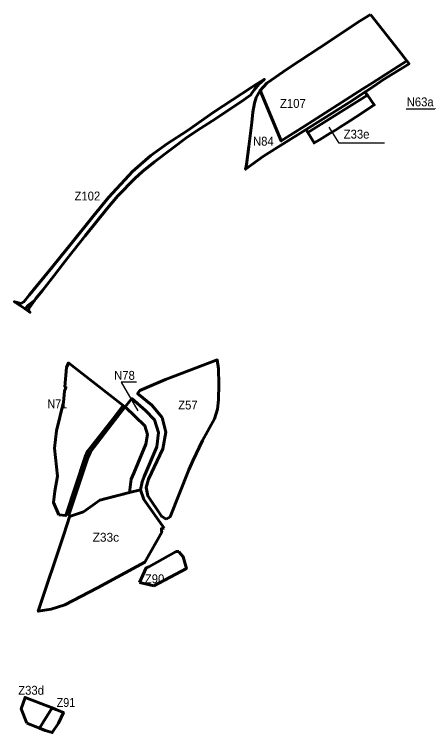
# Model space of a CAD drawing. Extents: x -650277 to -643425, y -1073980 to -1066720.
# Drawn here: x -648583 to -647467, y -1073980 to -1072042 of the extents above; entities that cross this region are included whole.
import ezdxf

# ---------------------------------------------------------------- set-up
doc = ezdxf.new("R2010")
doc.units = 0
doc.header["$LTSCALE"] = 9.6
for name, color, linetype, lineweight in [('15', 7, 'Continuous', 60), ('2', 7, 'Continuous', 40), ('24', 7, 'Continuous', 60), ('34', 7, 'Continuous', 60), ('42', 7, 'Continuous', 60), ('45', 7, 'Continuous', 60), ('48', 7, 'Continuous', 60), ('5', 7, 'Continuous', 60), ('59', 7, 'Continuous', 25), ('6', 7, 'Continuous', 60), ('60', 7, 'Continuous', 60), ('63', 7, 'Continuous', 25), ('8', 7, 'Continuous', 60), ('9', 7, 'Continuous', 60)]:
    doc.layers.add(name, color=color, linetype=linetype, lineweight=lineweight)

msp = doc.modelspace()

# ---------------------------------------------------------------- linework, layer by layer
at = {"layer": '15'}
msp.add_lwpolyline([(-647795.4, -1072352.415), (-647679.66, -1072279.15), (-647637.082, -1072251.377), (-647629.67, -1072259.82), (-647791.198, -1072360.119)], close=True, dxfattribs=at)
at = {"layer": '2', "lineweight": 60}
msp.add_lwpolyline([(-648303.791, -1072531.792), (-648258.165, -1072484.283), (-648237.406, -1072465.811), (-648205.298, -1072439.308), (-648116.32, -1072373.44), (-648079.76, -1072348.46), (-648050.276, -1072330.025), (-647969.894, -1072276.479), (-647944.45, -1072258.458), (-647941.77, -1072254.45), (-647934.9, -1072244.55), (-647923.16, -1072229.85), (-647908.5, -1072217.29), (-647933.95, -1072233.18), (-647942.21, -1072238.54), (-648046.69, -1072306.3), (-648117.12, -1072356), (-648169.81, -1072390.035), (-648214.73, -1072422.41), (-648264.618, -1072466.244), (-648274.53, -1072476.196), (-648328.847, -1072535.816), (-648369.37, -1072585.645), (-648431.557, -1072662.77), (-648459.243, -1072696.417), (-648481.468, -1072723.736), (-648543.255, -1072800.016), (-648557.588, -1072817.727), (-648565.726, -1072822.048), (-648583.407, -1072817.256), (-648564.86, -1072829.45), (-648554.22, -1072836.89), (-648541.102, -1072846.281), (-648545.462, -1072840.329), (-648544.632, -1072835.177), (-648524.979, -1072808.383), (-648507.503, -1072786.605), (-648476.204, -1072746.1), (-648452.274, -1072715.637), (-648439.912, -1072699.826), (-648391.796, -1072639.344), (-648333.178, -1072565.837)], close=True, dxfattribs=at)
at = {"layer": '24'}
msp.add_lwpolyline([(-648549.76, -1073954.86), (-648515.333, -1073968.584), (-648498, -1073940), (-648481.749, -1073913.76), (-648554.42, -1073885.092), (-648564.75, -1073915.91)], close=True, dxfattribs=at)
at = {"layer": '34'}
for points in [[(-647621.97, -1072041.73), (-647649.76, -1072059.06), (-647683.63, -1072081.94), (-647730.53, -1072112.84), (-647814.58, -1072167.67), (-647845.58, -1072188.94), (-647901.91, -1072227.6), (-647919.68, -1072247.09), (-647862.615, -1072383.084)], [(-647523.71, -1072167.071), (-647545.44, -1072139.35), (-647621.97, -1072041.73)], [(-647862.615, -1072383.084), (-647800.2, -1072343.615), (-647642.504, -1072242.974), (-647616.719, -1072226.154), (-647523.71, -1072167.071)]]:
    msp.add_lwpolyline(points, dxfattribs=at)
at = {"layer": '42'}
for points in [[(-647637.082, -1072251.377), (-647611.306, -1072234.563), (-647589.02, -1072219.66), (-647517.51, -1072174.98), (-647523.71, -1072167.071), (-647616.719, -1072226.154), (-647642.504, -1072242.974), (-647800.2, -1072343.615)], [(-647800.2, -1072343.615), (-647862.615, -1072383.084), (-647919.68, -1072247.09), (-647930.36, -1072266.38), (-647934.86, -1072280.99), (-647939.26, -1072306.1), (-647942.54, -1072333.82), (-647950.2, -1072398.61), (-647956.786, -1072446.511), (-647958.82, -1072459.74), (-647910.27, -1072424.51), (-647857.52, -1072391.14), (-647795.4, -1072352.415)], [(-647795.4, -1072352.415), (-647679.66, -1072279.15), (-647637.082, -1072251.377)]]:
    msp.add_lwpolyline(points, dxfattribs=at)
at = {"layer": '45'}
for points in [[(-648463.25, -1073392.125), (-648444.523, -1073394.235), (-648392.43, -1073235.98), (-648384.6, -1073219.54), (-648315.955, -1073131.889), (-648289.148, -1073097.66), (-648437.643, -1072982.601), (-648442.187, -1072994.5), (-648447.043, -1073046.967), (-648444.11, -1073048.69), (-648448.1, -1073058.393)], [(-648448.1, -1073058.393), (-648450.875, -1073088.375), (-648469.875, -1073165.5), (-648475.437, -1073212.375), (-648466.687, -1073288.25), (-648474.5, -1073328.75), (-648477.562, -1073358.875), (-648463.25, -1073392.125)], [(-648272.642, -1073332.558), (-648268, -1073296), (-648261, -1073280), (-648228, -1073202), (-648224, -1073176), (-648231, -1073152), (-648283.884, -1073101.15), (-648311.798, -1073137.127), (-648378.17, -1073222.67), (-648385.09, -1073238.58), (-648436.857, -1073395.099)], [(-648397.062, -1073384.375), (-648378.125, -1073370.875), (-648352.312, -1073353), (-648314.687, -1073343.25), (-648272.642, -1073332.558)], [(-648436.857, -1073395.099), (-648432.187, -1073395.625), (-648397.062, -1073384.375)]]:
    msp.add_lwpolyline(points, dxfattribs=at)
at = {"layer": '48'}
msp.add_lwpolyline([(-648231, -1073152), (-648224, -1073176), (-648228, -1073202), (-648261, -1073280), (-648268, -1073296), (-648272.642, -1073332.558), (-648243.08, -1073325.04), (-648237.98, -1073303.4), (-648232.64, -1073289.31), (-648198.7, -1073209.08), (-648194.2, -1073170.13), (-648205.04, -1073136.07), (-648228.91, -1073110.54), (-648266.38, -1073078.59), (-648283.884, -1073101.15)], close=True, dxfattribs=at)
at = {"layer": '5'}
for points in [[(-648272.642, -1073332.558), (-648352.312, -1073353), (-648397.062, -1073384.375)], [(-648179.07, -1073428.81), (-648233.36, -1073350.68), (-648243.08, -1073325.04), (-648272.642, -1073332.558)], [(-648397.062, -1073384.375), (-648432.187, -1073395.625), (-648433.206, -1073395.51), (-648449.599, -1073445.278)], [(-648447.06, -1073635.39), (-648358.69, -1073589.35), (-648230.81, -1073520.18), (-648185.34, -1073438.91), (-648185.82, -1073435.12), (-648186.46, -1073430.01), (-648183.46, -1073429.52), (-648179.07, -1073428.81)], [(-648449.599, -1073445.278), (-648518.867, -1073652.836), (-648483.58, -1073646.7), (-648447.06, -1073635.39), (-648447.06, -1073635.39)]]:
    msp.add_lwpolyline(points, dxfattribs=at)
at = {"layer": '6'}
msp.add_lwpolyline([(-648541.103, -1072846.28), (-648545.462, -1072840.329), (-648544.632, -1072835.177), (-648528.445, -1072813.109), (-648547.37, -1072827.71), (-648554.22, -1072836.89)], close=True, dxfattribs=at)
at = {"layer": '60'}
msp.add_line((-648245.341, -1073575.152), (-648207, -1073584), dxfattribs=at)
for points in [[(-648139.56, -1073491.4), (-648146.4, -1073491.55), (-648220.42, -1073532.43), (-648227.63, -1073535.89), (-648245.341, -1073575.152)], [(-648207, -1073584), (-648119, -1073537), (-648127.31, -1073505.75), (-648138.41, -1073493.62), (-648139.56, -1073491.4)]]:
    msp.add_lwpolyline(points, dxfattribs=at)
msp.add_lwpolyline([(-648515.333, -1073968.584), (-648499.84, -1073974.76), (-648480.86, -1073980.25), (-648464.44, -1073954.69), (-648451.05, -1073925.87), (-648471, -1073918), (-648481.749, -1073913.76)], close=True, dxfattribs=at)
at = {"layer": '63'}
msp.add_line((-647525, -1072297), (-647387, -1072297), dxfattribs=at)
for points in [[(-647584, -1072389), (-647706, -1072389), (-647733, -1072346)], [(-648254, -1073034), (-648295, -1073034), (-648250, -1073112)]]:
    msp.add_lwpolyline(points, dxfattribs=at)
at = {"layer": '8'}
msp.add_lwpolyline([(-647629.67, -1072259.82), (-647611.51, -1072286.26), (-647648.09, -1072309.95), (-647688.26, -1072336.06), (-647702.35, -1072345.14), (-647716.62, -1072353.95), (-647730.97, -1072362.6), (-647745.32, -1072371.26), (-647759.68, -1072379.91), (-647774.04, -1072388.57), (-647791.198, -1072360.119)], close=True, dxfattribs=at)
at = {"layer": '9'}
for points in [[(-648030.86, -1073039.71), (-648032.09, -1072998.65), (-648035.592, -1072974.222), (-648175.061, -1073027.551), (-648244.214, -1073056.657), (-648250.491, -1073064.698), (-648212.22, -1073096.39), (-648184.37, -1073129.89)], [(-648101.67, -1073246.63), (-648075.34, -1073191.93), (-648043.29, -1073132.97), (-648034.43, -1073107.07), (-648031.8, -1073082.07), (-648030.86, -1073039.71)], [(-648184.37, -1073129.89), (-648174.03, -1073168.94), (-648182.12, -1073214.56), (-648221.39, -1073296.24), (-648227.75, -1073318.75), (-648223.03, -1073341.59), (-648186.47, -1073396.47), (-648173.38, -1073404.03)], [(-648173.38, -1073404.03), (-648162.55, -1073397.4), (-648112.36, -1073270.87), (-648101.67, -1073246.63)]]:
    msp.add_lwpolyline(points, dxfattribs=at)

# ---------------------------------------------------------------- texts
at = {"layer": '59', "width": 0.95}
msp.add_text('Z102', height=24, dxfattribs=at).set_placement((-648421, -1072544))
at = {"layer": '63'}
for s, width, p in [('Z107', 0.95, (-647866, -1072294)), ('N63a', 0.95, (-647524, -1072290)), ('Z33e', 0.95, (-647694, -1072377)), ('N84', 0.95, (-647939, -1072396)), ('N78', 0.95, (-648314, -1073028)), ('N71', 0.9, (-648494, -1073105)), ('Z57', 0.95, (-648141, -1073108)), ('Z90', 0.95, (-648231, -1073577)), ('Z33d', 0.95, (-648573, -1073878)), ('Z91', 0.9, (-648469, -1073911))]:
    msp.add_text(s, height=24, dxfattribs=dict(at, width=width)).set_placement(p)
msp.add_text('Z33c', height=24, dxfattribs=at).set_placement((-648372, -1073465))

doc.saveas('drawing.dxf')
